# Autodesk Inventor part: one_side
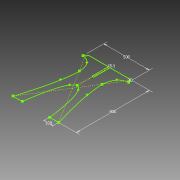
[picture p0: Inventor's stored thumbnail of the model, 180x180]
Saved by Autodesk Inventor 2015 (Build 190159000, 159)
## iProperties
Created: 2017-06
Part Number: one_side
Material: Generic
Document SubType Name: Modeling
Designer: mcalderon
Density: 1 g/cm^3
Appearance: Default
Author: mcalderon
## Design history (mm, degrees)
sketch "Sketch1"
  geometry: L1 (250, 364)-(250, 382); L2 (-250, -400)-(250, 400); L3 (250, -400)-(-250, 400); L4 (250, -400)-(150, -400); L5 (-250, 364)-(-250, 382); L6 (9.5, 220.487)-(9.5, 400); L7 (-9, 400)-(-9, 220.487); L8 (-8.5, 52)-(9.5, 400); L9 (9, 52)-(-9, 400); L10 (-9, 220.487)-(9.5, 220.487); L11 (230, 400)-(9.5, 400); L12 (-230, 400)-(-230, 382); L13 (230, 400)-(230, 382); L14 (-250, 382)-(-230, 382); L15 (230, 382)-(250, 382); L16 (-9, 382)-(-8.069, 382); L17 (8.569, 382)-(9.5, 382); L18 (-250, -400)-(-150, -400); L19 (-9, 400)-(-230, 400); 11 further points
  constraints: 38 end point, 5 point on line, 4 perpendicular, 2 midpoint, 1 horizontal, 1 parallel, 1 vertical, 21 other
  dimensions: "d2" = 500 distance of L3.end L2.end; "d3" = 800 distance of L2.end L3.start; "d4" = 100 distance of L4.start L4.end; "d5" = 18.5 distance of L7.start L6.end; "d10" = 20 distance of L11.start L2.end
other parameters: "d7" = 18, "d8" = 18
